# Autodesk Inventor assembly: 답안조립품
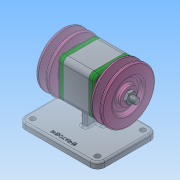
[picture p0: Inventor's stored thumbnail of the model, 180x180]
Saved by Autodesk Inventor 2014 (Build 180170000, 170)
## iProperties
Created: 2020-11
Part Number: 답안조립품
Document SubType Name: Assembly
Designer: NET
Author: NET
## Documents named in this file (10)
- C:\Users\NET\Desktop\701106V1030\답안조립품.iam
- C:\Users\NET\Desktop\701106V1030\답안본체.ipt
- C:\Users\NET\Desktop\701106V1030\커버.ipt
- C:\Users\NET\Desktop\701106V1030\축.ipt
- C:\Users\NET\Desktop\701106V1030\베어링 6004.ipt
- C:\Users\NET\Desktop\701106V1030\오일 실 17 30 5.ipt
- C:\Users\NET\Desktop\701106V1030\키 5 x 5 x 12.ipt
- C:\Users\NET\Desktop\701106V1030\V-벨트풀리.ipt
- C:\Users\NET\Desktop\701106V1030\볼트 M4.ipt
- C:\Users\NET\Desktop\701106V1030\너트 M10x1.ipt
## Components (2 placed, 1 different names)
1. V-벨트풀리:1
2. V-벨트풀리:2
